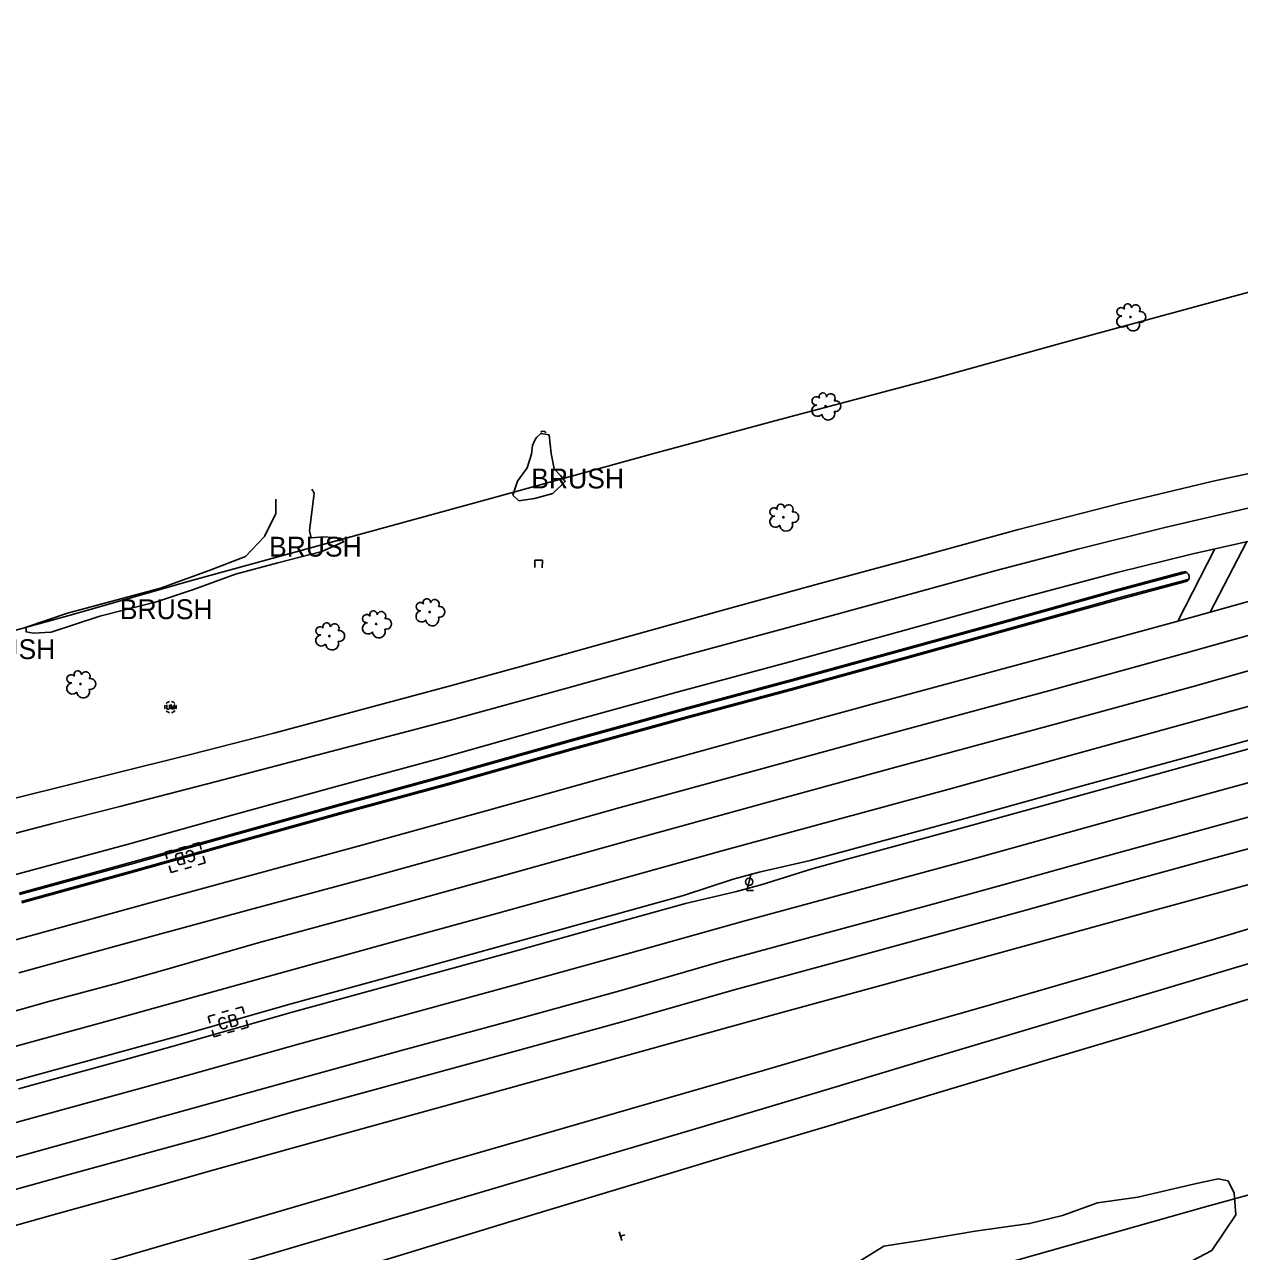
# Model space of a CAD drawing. Extents: x 2129547 to 2134906, y 657330 to 659734.
# Drawn here: x 2133315.8 to 2133745, y 658697 to 659130.2 of the extents above; entities that cross this region are included whole.
import ezdxf

# ---------------------------------------------------------------- set-up
doc = ezdxf.new("R2010")
doc.units = 0
for name, color, linetype in [('Default', 7, 'Continuous'), ('DR_X_Cells', 7, 'Continuous'), ('DR_X_Culvert', 7, 'Continuous'), ('LT_X_Poles', 7, 'Continuous'), ('PM_X_Edge_Line', 7, 'Continuous'), ('PM_X_Lane_Line', 7, 'Continuous'), ('PM_X_Transverse_Line', 7, 'Continuous'), ('PV_X_Curb', 7, 'Continuous'), ('PV_X_EOP2', 7, 'Continuous'), ('PV_X_Shoulder', 7, 'Continuous'), ('RD_X_Concrete_Barrier', 7, 'Continuous'), ('RD_X_Fence', 7, 'Continuous'), ('SN_X_Public', 7, 'Continuous'), ('UT_X_Unknown_Cells', 7, 'Continuous'), ('VG_X_Cells', 7, 'Continuous'), ('VG_X_Shrub_Line_Lt', 7, 'Continuous'), ('VG_X_Text', 7, 'Continuous'), ('VG_X_Tree_Line_Lt', 7, 'Continuous')]:
    doc.layers.add(name, color=color, linetype=linetype)

# ---------------------------------------------------------------- blocks, each defined once
blk = doc.blocks.new('PIPE')
at = {"layer": 'Default'}
for p, q in [((0.135, 0.067), (0, 0.067)), ((0, 0.067), (0, -0.067)), ((0, -0.067), (0.135, -0.067))]:
    blk.add_line(p, q, dxfattribs=at)
blk = doc.blocks.new('CULVERT')
at = {"layer": 'Default'}
blk.add_lwpolyline([(-0.0508, 0.1143), (0, 0.0635), (0, -0.0635), (-0.0508, -0.1143)], dxfattribs=at)
blk = doc.blocks.new('LPOLE')
at = {"layer": 'LT_X_Poles'}
blk.add_lwpolyline([(0.01, 0.0375), (-0.01, -0.0385), (0.02, -0.0385)], dxfattribs=at)
blk.add_circle((0, 0), 0.0165, dxfattribs=at)
blk = doc.blocks.new('SGN1P')
at = {"layer": 'SN_X_Public'}
for p, q in [((0, 0), (-0.02032, 0)), ((0, 0.02032), (0, -0.02032))]:
    blk.add_line(p, q, dxfattribs=at)
blk = doc.blocks.new('TREE')
at = {"layer": 'VG_X_Cells'}
blk.add_circle((0, 0), 0.00305, dxfattribs=at)
for centre, radius, start, end in [((-0.0125, 0.0428), 0.0167, 354.0047, 205.9741), ((0.0232, 0.0359), 0.0197, 323.83, 165.0376), ((-0.0362, -0.0197), 0.0251, 96.1722, 320.5737), ((-0.042, 0.0237), 0.0187, 39.0625, 279.5412), ((0.0439, 0.0005), 0.0243, 259.1453, 101.4596), ((0.012, -0.0331), 0.029, 184.9476, 19.4572)]:
    blk.add_arc(centre, radius, start, end, dxfattribs=at)
blk = doc.blocks.new('UMH')
at = {"layer": 'UT_X_Unknown_Cells'}
for p, q in [((-0.017, 0.0104), (-0.017, -0.0059)), ((-0.0042, 0.0104), (-0.0042, -0.0059))]:
    blk.add_line(p, q, dxfattribs=at)
blk.add_lwpolyline([(0.0024, -0.01), (0.0024, 0.0104), (0.0099, -0.01), (0.0174, 0.0104), (0.0174, -0.01)], dxfattribs=at)
for centre, radius, start, end in [((0, 0), 0.0254, 160.0169, 200.0392), ((0, 0), 0.0254, 100.0806, 140.0721), ((0, 0), 0.0254, 40.0577, 80.1061), ((0, 0), 0.0254, 340.0169, 20.0392), ((0, 0), 0.0254, 220.0577, 260.0473), ((-0.0106, -0.0029), 0.00708, 205.1924, 334.8076), ((0, 0), 0.0254, 280.0114, 320.0264)]:
    blk.add_arc(centre, radius, start, end, dxfattribs=at)
blk = doc.blocks.new('POINT_DISPLAY')
at = {"layer": 'Default'}
blk.add_line((0, 0), (0, 0), dxfattribs=at)
blk = doc.blocks.new('GCB-X')
at = {"layer": 'Default'}
for p, q in [((-0.0317, 0.019), (-0.019, 0.019)), ((-0.0317, 0.0063), (-0.0317, 0.019)), ((-0.0063, 0.019), (0.0063, 0.019)), ((0.0034, 0.0007), (0.0124, 0.0007)), ((0.019, 0.019), (0.0317, 0.019)), ((0.0317, 0.0063), (0.0317, 0.019)), ((-0.0317, -0.019), (-0.0317, -0.0063)), ((-0.0317, -0.019), (-0.019, -0.019)), ((-0.0063, -0.019), (0.0063, -0.019)), ((0.019, -0.019), (0.0317, -0.019)), ((0.0317, -0.019), (0.0317, -0.0063))]:
    blk.add_line(p, q, dxfattribs=at)
blk.add_lwpolyline([(0.0116, 0.0099), (0.0034, 0.0099), (0.0034, -0.0104), (0.0124, -0.0104)], dxfattribs=at)
for centre, radius, start, end in [((0.0071, 0), 0.0233, 164.8107, 195.1893), ((-0.0094, 0.0037), 0.00645, 21.5603, 158.4397), ((0.0101, 0.0051), 0.00501, 296.8207, 73.0013), ((0.0101, -0.0049), 0.00597, 292.0547, 67.9453), ((-0.0094, -0.0037), 0.00645, 201.5603, 338.4397)]:
    blk.add_arc(centre, radius, start, end, dxfattribs=at)
for p in [(0, 0.019), (0, 0.019), (-0.0317, 0), (0, 0), (0, 0), (0, 0), (0, -0.019), (0, -0.019), (0.0317, 0)]:
    blk.add_blockref('POINT_DISPLAY', p, dxfattribs=at)

msp = doc.modelspace()

# ---------------------------------------------------------------- linework, layer by layer
at = {"layer": 'PM_X_Edge_Line'}
for points in [[(2134076.98, 659040.11), (2134039.58, 659032.47), (2133995.73, 659023.51), (2133957.76, 659015.59), (2133918.23, 659007.39), (2133881.38, 658999.63), (2133836.62, 658990.22), (2133799.43, 658982.49), (2133764.9, 658975.21), (2133735.74, 658968.93), (2133703.2, 658961.23), (2133666.48, 658951.71), (2133630.91, 658941.98), (2133596.74, 658932.79), (2133563.73, 658923.72), (2133529.99, 658914.34), (2133494.1, 658904.34), (2133466.6, 658896.85), (2133432.86, 658887.72), (2133403.89, 658879.94), (2133374.41, 658872.42), (2133346.49, 658865.44), (2133329.04, 658861.1), (2133300.92, 658854.17)], [(2133309.7, 658768.6), (2133347.5, 658778.96), (2133367.51, 658784.47), (2133405.62, 658795.16), (2133448.61, 658806.96), (2133483.46, 658816.51), (2133522.93, 658827.51), (2133562.53, 658838.54), (2133602.55, 658849.42), (2133643.3, 658860.47), (2133686.86, 658872.53), (2133725.64, 658883.22), (2133766.44, 658894.43), (2133803.3, 658904.62), (2133840.04, 658914.78), (2133879.97, 658925.74), (2133918.52, 658936.37), (2133956.82, 658946.94), (2133995.76, 658957.55), (2134035.26, 658968.3), (2134076.56, 658979.89)], [(2134083.48, 658954.83), (2134042.19, 658943.24), (2134002.59, 658932.46), (2133963.69, 658921.87), (2133925.43, 658911.31), (2133886.87, 658900.67), (2133846.95, 658889.72), (2133810.23, 658879.56), (2133773.34, 658869.36), (2133732.54, 658858.16), (2133693.78, 658847.47), (2133650.17, 658835.4), (2133609.36, 658824.33), (2133569.43, 658813.47), (2133529.91, 658802.46), (2133490.38, 658791.45), (2133455.49, 658781.89), (2133412.58, 658770.11), (2133374.05, 658759.3), (2133354.39, 658753.89), (2133316.59, 658743.53), (2133275.25, 658732.12)], [(2133761.03, 658950.6), (2133728.54, 658943.33), (2133701.8, 658936.66), (2133662.8, 658926.3), (2133625.1, 658915.88), (2133585.31, 658904.93), (2133547.18, 658894.67), (2133507.02, 658883.64), (2133462.8, 658871.16), (2133425.07, 658860.86), (2133387.85, 658850.71), (2133352.86, 658840.89), (2133312.19, 658829.94)], [(2133300.07, 658803.6), (2133337.89, 658813.96), (2133358.39, 658819.61), (2133392.08, 658828.83), (2133434.98, 658840.46), (2133479.62, 658852.8), (2133523.07, 658864.95), (2133572.16, 658878.44), (2133618.64, 658891.13), (2133674.95, 658906.36), (2133722.33, 658919.3), (2133765.05, 658931.14)], [(2133283.96, 658698.16), (2133325.94, 658709.93), (2133362.52, 658720.04), (2133382.76, 658725.75), (2133415.39, 658734.86), (2133446.49, 658743.43), (2133481, 658753.01), (2133515.88, 658762.68), (2133547.13, 658771.3), (2133583.28, 658781.31), (2133617.02, 658790.56), (2133648.77, 658799.18), (2133685.56, 658809.34), (2133717.23, 658818.06), (2133753.97, 658828.1), (2133791.98, 658838.6), (2133832.99, 658849.73), (2133873.96, 658860.85), (2133913, 658871.48), (2133948.28, 658881.16), (2133981.44, 658890.27), (2134020.14, 658900.81), (2134061.11, 658912.35), (2134098.82, 658922.76)], [(2134100.25, 658917.23), (2134063.61, 658906.19), (2134030.5, 658896.13), (2133992.93, 658884.72), (2133952.23, 658872.51), (2133907.65, 658859.14), (2133870.19, 658847.84), (2133822.17, 658833.24), (2133782.71, 658821.22), (2133738.55, 658807.98), (2133692.7, 658794.41), (2133654.59, 658783.4), (2133617.25, 658772.7), (2133577.18, 658761.03), (2133541.61, 658750.79), (2133494, 658737.03), (2133462.99, 658727.98), (2133431.79, 658718.75), (2133387.92, 658705.89), (2133365.27, 658699.28), (2133330.15, 658689.11), (2133297.63, 658679.74)], [(2133300.81, 658650.13), (2133340.17, 658662.31), (2133370.93, 658671.87), (2133394.87, 658679.11), (2133427.09, 658689.08), (2133460.97, 658699.4), (2133496.37, 658710.22), (2133532.31, 658721.07), (2133564.53, 658730.83), (2133600.72, 658741.62), (2133635.89, 658752.26), (2133677.52, 658764.71), (2133710.02, 658774.41), (2133749.64, 658786.47), (2133791.16, 658798.85), (2133827.56, 658809.83), (2133864.21, 658820.91), (2133900.69, 658832.03), (2133931.82, 658841.63), (2133974.36, 658854.66), (2134018.27, 658867.93), (2134054.66, 658878.9), (2134088.9, 658889.31)]]:
    msp.add_lwpolyline(points, dxfattribs=at)
at = {"layer": 'PM_X_Lane_Line'}
for points in [[(2134118.93, 659037.07), (2134073.54, 659027.1), (2134032.75, 659018.71), (2133995.61, 659011.27), (2133962.39, 659004.33), (2133919.52, 658995.52), (2133877.54, 658986.95), (2133831.82, 658977.28), (2133792.35, 658968.95), (2133753.58, 658960.7), (2133718.63, 658952.54), (2133687.93, 658944.98), (2133659.01, 658937.36), (2133625.24, 658928.09), (2133585.58, 658917.3), (2133543.69, 658905.93), (2133507.33, 658895.86), (2133466.3, 658884.59), (2133424.01, 658873.52), (2133383.54, 658862.9), (2133349.44, 658854.08), (2133325.82, 658848.04), (2133297.69, 658840.83)], [(2133313.7, 658795.31), (2133339, 658802.3), (2133361.28, 658808.47), (2133395.15, 658817.54), (2133438.07, 658829.18), (2133482.76, 658841.53), (2133526.2, 658853.67), (2133575.25, 658867.16), (2133621.71, 658879.84), (2133678.02, 658895.07), (2133725.8, 658908.19), (2133763.55, 658918.78), (2133812.61, 658932.39), (2133855.72, 658944.34), (2133897.07, 658955.57), (2133937.39, 658966.63), (2133974.36, 658976.85), (2134011.24, 658987.04), (2134057.34, 658999.52), (2134095.74, 659010.12)], [(2134098.91, 658998.55), (2134060.5, 658987.95), (2134014.41, 658975.46), (2133977.55, 658965.28), (2133940.57, 658955.06), (2133900.23, 658943.99), (2133858.89, 658932.76), (2133815.81, 658920.83), (2133766.78, 658907.22), (2133728.61, 658896.45), (2133681.16, 658883.49), (2133624.85, 658868.26), (2133578.42, 658855.58), (2133529.4, 658842.11), (2133485.97, 658829.97), (2133441.24, 658817.61), (2133398.31, 658805.97), (2133364.46, 658796.21), (2133347.75, 658791.48), (2133325.2, 658785.49), (2133298.77, 658778.04)], [(2134082.7, 658942.15), (2134045.11, 658931.76), (2134004.55, 658920.87), (2133969.21, 658911.2), (2133933.79, 658901.38), (2133893.59, 658890.3), (2133855.02, 658879.79), (2133816.65, 658869.07), (2133773.41, 658857.23), (2133730.82, 658845.66), (2133696.89, 658836.35), (2133666.57, 658827.89), (2133635.33, 658819.28), (2133597.94, 658809.08), (2133562.69, 658799.56), (2133526.89, 658789.25), (2133487.16, 658778.31), (2133449.31, 658767.99), (2133406.68, 658756.3), (2133376.98, 658748.02), (2133351.87, 658741.08), (2133319.94, 658732.31), (2133288.5, 658723.61)], [(2134085.69, 658931.46), (2134048.03, 658921.05), (2134007.46, 658910.16), (2133972.15, 658900.5), (2133936.74, 658890.68), (2133896.5, 658879.69), (2133857.94, 658869.19), (2133818.5, 658858.38), (2133776.26, 658846.81), (2133733.66, 658835.25), (2133699.77, 658825.94), (2133669.46, 658817.48), (2133638.19, 658808.87), (2133600.77, 658798.65), (2133565.6, 658789.16), (2133529.81, 658778.86), (2133490.02, 658767.9), (2133452.16, 658757.57), (2133409.55, 658745.89), (2133379.74, 658737.38), (2133360.24, 658732.07), (2133330.22, 658723.85), (2133298.5, 658714.96)], [(2133285.43, 658660.84), (2133325.6, 658673.06), (2133366.78, 658685.54), (2133391.32, 658692.78), (2133423.26, 658702.17), (2133460.05, 658712.86), (2133499.85, 658724.58), (2133554.8, 658740.88), (2133599.29, 658754.21), (2133636.1, 658765.28), (2133676.03, 658777.16), (2133716.18, 658788.97), (2133754.3, 658800.38), (2133789.1, 658810.81), (2133832.71, 658824.03), (2133874.01, 658836.57), (2133911.3, 658847.78), (2133953.4, 658860.48), (2133993.83, 658872.75), (2134036.36, 658885.82), (2134070.45, 658896.19), (2134110.34, 658908.07)]]:
    msp.add_lwpolyline(points, dxfattribs=at)
at = {"layer": 'PM_X_Transverse_Line'}
for p, q in [((2133723.21, 658919.54), (2133736.3, 658945.07)), ((2133734.58, 658922.69), (2133747.58, 658947.59))]:
    msp.add_line(p, q, dxfattribs=at)
at = {"layer": 'PV_X_Curb'}
for points in [[(2133726.42, 658936.66), (2133725.46, 658936.44), (2133701.2, 658930), (2133664.56, 658919.78), (2133626.9, 658909.38), (2133587.08, 658898.42), (2133548.96, 658888.16), (2133508.83, 658877.14), (2133464.61, 658864.65), (2133426.84, 658854.35), (2133388.46, 658843.65), (2133354.62, 658834.11), (2133313.99, 658822.98)], [(2133727.04, 658934.3), (2133725.96, 658934.01), (2133701.86, 658927.58), (2133665.23, 658917.37), (2133627.56, 658906.97), (2133587.74, 658896.01), (2133549.61, 658885.74), (2133509.5, 658874.73), (2133465.27, 658862.24), (2133427.5, 658851.94), (2133389.02, 658841.2), (2133355.25, 658831.69), (2133314.65, 658820.57)]]:
    msp.add_lwpolyline(points, dxfattribs=at)
at = {"layer": 'PV_X_EOP2'}
for points in [[(2134076.98, 659040.11), (2134039.58, 659032.47), (2133995.73, 659023.51), (2133957.76, 659015.59), (2133918.23, 659007.39), (2133881.38, 658999.63), (2133836.62, 658990.22), (2133799.43, 658982.49), (2133764.9, 658975.21), (2133735.74, 658968.93), (2133703.2, 658961.23), (2133666.48, 658951.71), (2133630.91, 658941.98), (2133596.74, 658932.79), (2133563.73, 658923.72), (2133529.99, 658914.34), (2133494.1, 658904.34), (2133466.6, 658896.85), (2133432.86, 658887.72), (2133403.89, 658879.94), (2133374.41, 658872.42), (2133346.49, 658865.44), (2133329.04, 658861.1), (2133300.92, 658854.17)], [(2133309.7, 658768.6), (2133347.5, 658778.96), (2133367.51, 658784.47), (2133405.62, 658795.16), (2133448.61, 658806.96), (2133483.46, 658816.51), (2133522.93, 658827.51), (2133562.53, 658838.54), (2133602.55, 658849.42), (2133643.3, 658860.47), (2133686.86, 658872.53), (2133725.64, 658883.22), (2133766.44, 658894.43), (2133803.3, 658904.62), (2133840.04, 658914.78), (2133879.97, 658925.74), (2133918.52, 658936.37), (2133956.82, 658946.94), (2133995.76, 658957.55), (2134035.26, 658968.3), (2134076.56, 658979.89)], [(2134083.48, 658954.83), (2134042.19, 658943.24), (2134002.59, 658932.46), (2133963.69, 658921.87), (2133925.43, 658911.31), (2133886.87, 658900.67), (2133846.95, 658889.72), (2133810.23, 658879.56), (2133773.34, 658869.36), (2133732.54, 658858.16), (2133693.78, 658847.47), (2133650.17, 658835.4), (2133609.36, 658824.33), (2133569.43, 658813.47), (2133529.91, 658802.46), (2133490.38, 658791.45), (2133455.49, 658781.89), (2133412.58, 658770.11), (2133374.05, 658759.3), (2133354.39, 658753.89), (2133316.59, 658743.53), (2133275.25, 658732.12)], [(2133761.03, 658950.6), (2133728.54, 658943.33), (2133701.8, 658936.66), (2133662.8, 658926.3), (2133625.1, 658915.88), (2133585.31, 658904.93), (2133547.18, 658894.67), (2133507.02, 658883.64), (2133462.8, 658871.16), (2133425.07, 658860.86), (2133387.85, 658850.71), (2133352.86, 658840.89), (2133312.19, 658829.94)], [(2133300.07, 658803.6), (2133337.89, 658813.96), (2133358.39, 658819.61), (2133392.08, 658828.83), (2133434.98, 658840.46), (2133479.62, 658852.8), (2133523.07, 658864.95), (2133572.16, 658878.44), (2133618.64, 658891.13), (2133674.95, 658906.36), (2133722.33, 658919.3), (2133765.05, 658931.14)], [(2133283.96, 658698.16), (2133325.94, 658709.93), (2133362.52, 658720.04), (2133382.76, 658725.75), (2133415.39, 658734.86), (2133446.49, 658743.43), (2133481, 658753.01), (2133515.88, 658762.68), (2133547.13, 658771.3), (2133583.28, 658781.31), (2133617.02, 658790.56), (2133648.77, 658799.18), (2133685.56, 658809.34), (2133717.23, 658818.06), (2133753.97, 658828.1), (2133791.98, 658838.6), (2133832.99, 658849.73), (2133873.96, 658860.85), (2133913, 658871.48), (2133948.28, 658881.16), (2133981.44, 658890.27), (2134020.14, 658900.81), (2134061.11, 658912.35), (2134098.82, 658922.76)], [(2134100.25, 658917.23), (2134063.61, 658906.19), (2134030.5, 658896.13), (2133992.93, 658884.72), (2133952.23, 658872.51), (2133907.65, 658859.14), (2133870.19, 658847.84), (2133822.17, 658833.24), (2133782.71, 658821.22), (2133738.55, 658807.98), (2133692.7, 658794.41), (2133654.59, 658783.4), (2133617.25, 658772.7), (2133577.18, 658761.03), (2133541.61, 658750.79), (2133494, 658737.03), (2133462.99, 658727.98), (2133431.79, 658718.75), (2133387.92, 658705.89), (2133365.27, 658699.28), (2133330.15, 658689.11), (2133297.63, 658679.74)]]:
    msp.add_lwpolyline(points, dxfattribs=at)
at = {"layer": 'PV_X_Shoulder'}
msp.add_lwpolyline([(2133313.86, 658823.46), (2133354.5, 658834.6), (2133388.32, 658844.13), (2133426.71, 658854.84), (2133464.47, 658865.13), (2133508.7, 658877.62), (2133548.82, 658888.64), (2133586.95, 658898.9), (2133626.77, 658909.86), (2133664.43, 658920.26), (2133701.07, 658930.48), (2133724.74, 658936.76), (2133725.41, 658936.91), (2133725.92, 658936.88), (2133726.42, 658936.66), (2133726.99, 658936.11), (2133727.25, 658935.42), (2133727.21, 658934.72), (2133727.04, 658934.3), (2133726.8, 658933.96), (2133726.45, 658933.66), (2133725.66, 658933.39), (2133701.99, 658927.1), (2133665.36, 658916.89), (2133627.69, 658906.48), (2133587.87, 658895.53), (2133549.74, 658885.26), (2133509.64, 658874.25), (2133465.41, 658861.76), (2133427.63, 658851.46), (2133389.16, 658840.72), (2133355.38, 658831.21), (2133314.78, 658820.09)], dxfattribs=at)
at = {"layer": 'RD_X_Concrete_Barrier'}
for points in [[(2133769.49, 658883.34), (2133728.69, 658872.14), (2133689.92, 658861.45), (2133646.33, 658849.38), (2133605.56, 658838.33), (2133593.31, 658834.99), (2133575.27, 658830.86), (2133566.17, 658828.39), (2133548.57, 658822.71), (2133526.02, 658816.43), (2133486.52, 658805.42), (2133451.65, 658795.87), (2133408.7, 658784.08), (2133370.45, 658773.14), (2133350.6, 658767.68), (2133312.8, 658757.32)], [(2133313.6, 658754.43), (2133351.4, 658764.78), (2133371.21, 658770.24), (2133409.5, 658781.19), (2133452.44, 658792.98), (2133487.32, 658802.53), (2133526.83, 658813.54), (2133549.32, 658819.81), (2133567.3, 658824.03), (2133576.4, 658826.51), (2133594.07, 658832.09), (2133606.35, 658835.43), (2133647.13, 658846.49), (2133690.72, 658858.56), (2133729.49, 658869.24), (2133770.29, 658880.45)]]:
    msp.add_lwpolyline(points, dxfattribs=at)
at = {"layer": 'RD_X_Fence'}
for points in [[(2134118.14, 659130.16), (2134070.98, 659119.25), (2134019.86, 659107.98), (2133977.41, 659097.6), (2133937.58, 659086.88), (2133891.52, 659073.98), (2133829.38, 659057.65), (2133758.68, 659038.54), (2133682.08, 659017.72), (2133636.81, 659005.08), (2133582.59, 658990.71), (2133537.62, 658978.61), (2133480.02, 658962.66), (2133435.74, 658950.56), (2133375.25, 658933.98), (2133331.89, 658921.65)], [(2132862.2, 658871.41), (2132893.21, 658906.4), (2132919.58, 658910.31), (2132935.95, 658910.2), (2133025.5, 658908.09), (2133173.05, 658905.09), (2133177.13, 658884.47), (2133277.21, 658906.58), (2133331.89, 658921.65)], [(2133409.37, 658623.24), (2133432.34, 658629.66), (2133487.07, 658644.47), (2133549.03, 658661.67), (2133595.11, 658674.24), (2133645.48, 658687.97), (2133677.95, 658697.17), (2133733.37, 658712.84), (2133776.67, 658724.79), (2133828.23, 658738.5), (2133881.21, 658752.85), (2133931.92, 658766.78), (2133954.07, 658773.11)]]:
    msp.add_lwpolyline(points, dxfattribs=at)
at = {"layer": 'VG_X_Shrub_Line_Lt'}
msp.add_lwpolyline([(2133501.14, 658985.28), (2133501.87, 658978.69), (2133502.89, 658973.31), (2133505.11, 658970.93), (2133506.77, 658968.78), (2133502.46, 658964.6), (2133495.94, 658962.78), (2133490.44, 658961.97), (2133488.32, 658964), (2133489.97, 658968.97), (2133493.39, 658973.63), (2133494.81, 658978.52), (2133495.25, 658981.59), (2133496.01, 658983.39), (2133496.61, 658984.41), (2133498.22, 658985.81)], close=True, dxfattribs=at)
for points in [[(2133417.27, 658966.12), (2133418.14, 658964.69), (2133416.44, 658951.37), (2133417, 658948.88), (2133421.56, 658949.32), (2133427.44, 658948.77), (2133428.49, 658947.56), (2133420.84, 658944.11), (2133405.31, 658940.07), (2133390.35, 658936.07), (2133375.49, 658930.75), (2133362.44, 658926.39), (2133342.37, 658921.32), (2133325.13, 658915.63), (2133318.94, 658915.26), (2133316.39, 658915.69), (2133316.31, 658917.4), (2133330.93, 658922.29), (2133363.78, 658931.17), (2133380.96, 658937.39)], [(2133380.96, 658937.39), (2133393.84, 658942.33), (2133400.55, 658949.44), (2133404.51, 658957.5), (2133404.59, 658962.64)]]:
    msp.add_lwpolyline(points, dxfattribs=at)
at = {"layer": 'VG_X_Tree_Line_Lt'}
msp.add_lwpolyline([(2133607.54, 658691.6), (2133619.35, 658698.8), (2133632.16, 658700.87), (2133651.65, 658704.14), (2133670.84, 658706.8), (2133682.47, 658709.7), (2133694.84, 658714.17), (2133709.08, 658716.12), (2133728.73, 658720.72), (2133737.43, 658722.62), (2133740.93, 658721.92), (2133743.05, 658717.55), (2133743.66, 658709.95), (2133739.61, 658703.73), (2133735.27, 658697.32), (2133725.85, 658692.32)], dxfattribs=at)

# ---------------------------------------------------------------- block references
at = {"layer": 'DR_X_Cells', "xscale": 196.85}
for p, yscale, rotation in [((2133372.53, 658836.04), 196.85000000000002, -164.27081136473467), ((2133387.69, 658778.07), 196.85000000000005, 15.954577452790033)]:
    msp.add_blockref('GCB-X', p, dxfattribs=dict(at, yscale=yscale, rotation=rotation))
at = {"layer": 'DR_X_Culvert'}
for name, p, xscale, yscale, rotation in [('CULVERT', (2133499.08, 658986.57), 7.8740000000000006, 7.8740000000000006, 82.28117393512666), ('PIPE', (2133497.42, 658941.04), 19.685000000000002, 19.685, -91.18004425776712)]:
    msp.add_blockref(name, p, dxfattribs=dict(at, xscale=xscale, yscale=yscale, rotation=rotation))
at = {"layer": 'LT_X_Poles', "xscale": 78.74000000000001, "yscale": 78.74000000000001}
msp.add_blockref('LPOLE', (2133571.74, 658827.46), dxfattribs=at)
at = {"layer": 'SN_X_Public', "xscale": 78.74000000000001, "yscale": 78.74, "rotation": -163.6850229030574}
msp.add_blockref('SGN1P', (2133526.29, 658702.4), dxfattribs=at)
at = {"layer": 'UT_X_Unknown_Cells', "xscale": 78.74000000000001, "yscale": 78.74000000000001}
msp.add_blockref('UMH', (2133367.34, 658889.2), dxfattribs=at)
at = {"layer": 'VG_X_Cells', "xscale": 78.74000000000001, "yscale": 78.74000000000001}
for p in [(2133706.48, 659026.88), (2133598.75, 658995.41), (2133583.88, 658956.2), (2133458.89, 658922.76), (2133439.99, 658918.52), (2133423.49, 658914.24), (2133335.54, 658897.3)]:
    msp.add_blockref('TREE', p, dxfattribs=at)

# ---------------------------------------------------------------- texts
at = {"layer": 'VG_X_Text'}
for p in [(2133494.79, 658966.39), (2133402.14, 658942.31), (2133349.44, 658920.23), (2133293.88, 658906.12)]:
    msp.add_text('BRUSH', height=7, dxfattribs=at).set_placement(p)

doc.saveas('drawing.dxf')
